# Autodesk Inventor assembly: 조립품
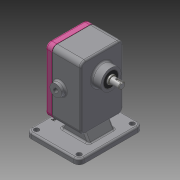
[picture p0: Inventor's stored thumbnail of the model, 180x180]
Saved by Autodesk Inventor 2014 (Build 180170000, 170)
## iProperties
Created: 2020-04
Part Number: 조립품
Document SubType Name: Assembly
Designer: kh
Author: kh
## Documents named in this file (11)
- C:\Users\kh\Desktop\700407V1024\조립품.iam
- C:\Users\kh\Desktop\700407V1024\본체.ipt
- C:\Users\kh\Desktop\700407V1024\개스킷.ipt
- C:\Users\kh\Desktop\700407V1024\메인축.ipt
- C:\Users\kh\Desktop\700407V1024\베어링부시.ipt
- C:\Users\kh\Desktop\700407V1024\볼트 M5.ipt
- C:\Users\kh\Desktop\700407V1024\서브축.ipt
- C:\Users\kh\Desktop\700407V1024\스퍼기어.ipt
- C:\Users\kh\Desktop\700407V1024\오일 실 16 28 7.ipt
- C:\Users\kh\Desktop\700407V1024\커버.ipt
- C:\Users\kh\Desktop\700407V1024\키 6 x 6 x 18.ipt
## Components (1 placed, 1 different names)
1. 개스킷:1
